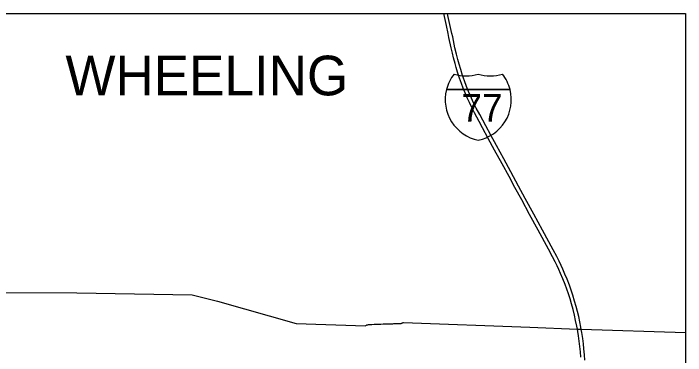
# Model space of a CAD drawing. Extents: x -12.1 to 34, y 0 to 22.
# Drawn here: x 7.88 to 10.59, y 18.927 to 20.306 of the extents above; entities that cross this region are included whole.
import ezdxf

# ---------------------------------------------------------------- set-up
doc = ezdxf.new("R2010")
doc.units = 0
for name, color, linetype in [('GM_X_Interstate_Route', 7, 'Continuous'), ('GM_X_Interstate_Shield', 7, 'Continuous'), ('GM_X_Township', 7, 'Continuous'), ('GM_X_Township_Text', 7, 'Continuous'), ('SH_Text', 7, 'Continuous')]:
    doc.layers.add(name, color=color, linetype=linetype)

msp = doc.modelspace()

# ---------------------------------------------------------------- linework, layer by layer
at = {"layer": 'GM_X_Interstate_Route'}
for points in [[(10.1674, 18.921), (10.1658, 18.9425), (10.1637, 18.9634), (10.1611, 18.9854), (10.1581, 19.0067), (10.1552, 19.0245), (10.1537, 19.0329), (10.1513, 19.0457), (10.1466, 19.0686), (10.1419, 19.0896), (10.1361, 19.1128), (10.13, 19.1353), (10.1241, 19.1554), (10.1177, 19.1754), (10.1113, 19.1942), (10.104, 19.2138), (10.0949, 19.2366), (10.0862, 19.2575), (10.0791, 19.2735), (10.0718, 19.2894), (10.0643, 19.3046), (10.0536, 19.3253), (10.0371, 19.356), (9.9957, 19.4323), (9.961, 19.4963), (9.9292, 19.5546), (9.9017, 19.6052), (9.8781, 19.6488), (9.8504, 19.6994), (9.8199, 19.7557), (9.7945, 19.8023), (9.7713, 19.8447), (9.7575, 19.8703), (9.7388, 19.9058), (9.7278, 19.9276), (9.7182, 19.9476), (9.7098, 19.9661), (9.7013, 19.9859), (9.6937, 20.0048), (9.6863, 20.0244), (9.6789, 20.0452), (9.6708, 20.0695), (9.6648, 20.0889), (9.6604, 20.104), (9.6541, 20.1276), (9.6497, 20.1457), (9.6446, 20.1678), (9.6357, 20.2094), (9.6322, 20.2255), (9.6253, 20.2578), (9.6149, 20.3063)], [(10.1833, 18.9081), (10.1819, 18.9307), (10.18, 18.9539), (10.1779, 18.9742), (10.175, 18.9961), (10.1713, 19.0203), (10.1692, 19.0325), (10.1677, 19.0415), (10.1635, 19.0632), (10.1589, 19.0842), (10.1539, 19.1051), (10.1486, 19.1254), (10.1425, 19.1467), (10.1351, 19.1706), (10.1285, 19.1904), (10.1212, 19.2107), (10.112, 19.2346), (10.1034, 19.2556), (10.0951, 19.2748), (10.0879, 19.2907), (10.0798, 19.3075), (10.0703, 19.3261), (10.0562, 19.3529), (10.013, 19.4328), (9.9774, 19.4976), (9.9433, 19.5606), (9.9163, 19.6103), (9.8847, 19.668), (9.8565, 19.7196), (9.8275, 19.7735), (9.8046, 19.8154), (9.784, 19.8533), (9.7597, 19.8984), (9.7462, 19.9242), (9.7367, 19.9429), (9.7307, 19.9555), (9.7223, 19.9741), (9.7148, 19.9918), (9.7066, 20.0124), (9.6984, 20.0342), (9.6909, 20.0557), (9.6831, 20.0801), (9.6768, 20.1013), (9.6714, 20.121), (9.666, 20.1425), (9.6602, 20.1675), (9.6508, 20.2119), (9.6477, 20.2258), (9.6319, 20.2983), (9.6302, 20.3063)]]:
    msp.add_lwpolyline(points, dxfattribs=at)
at = {"layer": 'GM_X_Interstate_Shield'}
for p, q in [((9.6259, 19.9993), (9.8821, 19.9993)), ((9.8821, 19.9993), (9.6259, 19.9993)), ((9.8821, 19.9993), (9.6259, 19.9993))]:
    msp.add_line(p, q, dxfattribs=at)
for centre, start, end in [((9.7873, 19.9585), 141.669, 165.8066), ((9.7054, 20.2209), 253.0091, 286.9909), ((9.8027, 20.2209), 253.0091, 286.9909), ((9.7207, 19.9585), 14.1934, 38.331), ((9.7873, 19.9585), 165.8066, 258.463), ((9.7207, 19.9585), 281.537, 14.1934)]:
    msp.add_arc(centre, 0.1665, start, end, dxfattribs=at)
at = {"layer": 'GM_X_Township'}
msp.add_lwpolyline([(7.1234, 19.1821), (8.1356, 19.1805), (8.6009, 19.1725), (8.7028, 19.1468), (9.0199, 19.0558), (9.2988, 19.0474), (9.3006, 19.0486), (9.3036, 19.0501), (9.3054, 19.0508), (9.3071, 19.0513), (9.3087, 19.0516), (9.3109, 19.0521), (9.3139, 19.0523), (9.3178, 19.0525), (9.3244, 19.0528), (9.3348, 19.0533), (9.3436, 19.0537), (9.3611, 19.0543), (9.3702, 19.0546), (9.3747, 19.0548), (9.3831, 19.0551), (9.3975, 19.0555), (9.4056, 19.0556), (9.4092, 19.0557), (9.4138, 19.0558), (9.4177, 19.0558), (9.4217, 19.0559), (9.4251, 19.0559), (9.4279, 19.0559), (9.429, 19.0559), (9.4312, 19.0559), (9.4323, 19.0559), (9.434, 19.056), (9.4361, 19.056), (9.4371, 19.0561), (9.4385, 19.0561), (9.4414, 19.0566), (9.4433, 19.057), (9.4451, 19.0575), (9.4471, 19.0581), (9.449, 19.0588), (9.4518, 19.0602), (9.4531, 19.061), (9.9615, 19.0417), (10.1535, 19.0334), (10.169, 19.033), (10.5897, 19.02)], dxfattribs=at)
at = {"layer": 'SH_Text'}
msp.add_lwpolyline([(2.8817, 20.3063), (10.5897, 20.3063), (10.5897, 10.9773), (2.8817, 10.9773)], close=True, dxfattribs=at)

# ---------------------------------------------------------------- texts
at = {"layer": 'GM_X_Interstate_Shield'}
msp.add_text('77', height=0.11097, dxfattribs=at).set_placement((9.6866, 19.8703))
at = {"layer": 'GM_X_Township_Text'}
msp.add_text('WHEELING', height=0.1598, rotation=0, dxfattribs=at).set_placement((8.0898, 19.9761))

doc.saveas('drawing.dxf')
